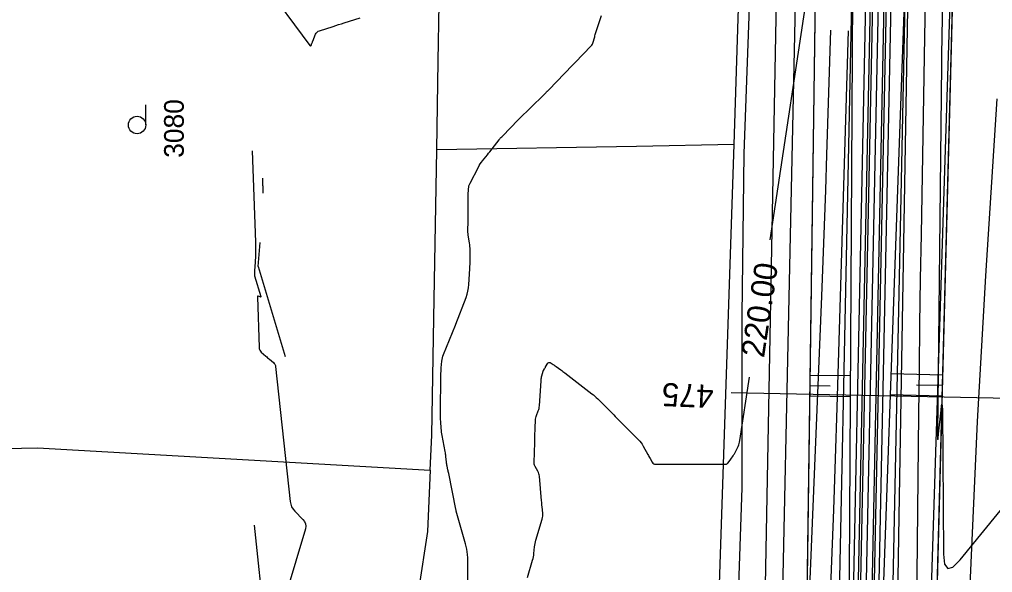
# Model space of a CAD drawing. Extents: x -534410 to -534262, y -1190162 to -1189584.
# Drawn here: x -534360.56 to -534318.59, y -1190105.52 to -1190081.68 of the extents above; entities that cross this region are included whole.
import ezdxf

# ---------------------------------------------------------------- set-up
doc = ezdxf.new("R2010")
doc.units = 0
for name, color, linetype in [('07_ELEKTRO', 7, 'Continuous'), ('30', 7, 'Continuous'), ('31', 7, 'Continuous'), ('40', 7, 'Continuous'), ('_linie', 7, 'Continuous'), ('_N_osa', 7, 'Continuous'), ('_N_tenká', 7, 'Continuous'), ('_N_tenká_velmi', 7, 'Continuous'), ('_N_text', 7, 'Continuous'), ('_přístup', 7, 'Continuous'), ('_tenka', 7, 'Continuous'), ('_velmi_tenka', 7, 'Continuous'), ('Default', 7, 'Continuous'), ('Hranice parcel', 7, 'Continuous'), ('Parcelní čísla', 7, 'Continuous'), ('Značky kultur', 7, 'Continuous')]:
    doc.layers.add(name, color=color, linetype=linetype)

msp = doc.modelspace()

# ---------------------------------------------------------------- linework, layer by layer
at = {"layer": '07_ELEKTRO'}
msp.add_lwpolyline([(-534340.501, -1190135.539), (-534331.273, -1190133.27), (-534330.81, -1190133.08), (-534330.32, -1190132.66), (-534330.24, -1190132.17), (-534330.24, -1190130.93), (-534330.14, -1190126.19), (-534329.99, -1190122.81), (-534329.79, -1190121.43), (-534329.75, -1190115.24), (-534329.64, -1190109.01), (-534329.39, -1190101.86), (-534329.4, -1190094.43), (-534329.31, -1190087.46), (-534329.03, -1190079.95)], dxfattribs=at)
at = {"layer": '30'}
for points in [[(-534322.214, -1190078.674), (-534322.64, -1190103.1), (-534322.669, -1190104.87), (-534322.696, -1190106.64)], [(-534328.187, -1190091.169), (-534326.393, -1190079.271)], [(-534350.068, -1190080.059), (-534348.04, -1190082.803), (-534348.025, -1190082.818), (-534348.012, -1190082.822), (-534348, -1190082.815), (-534347.99, -1190082.797), (-534347.952, -1190082.702), (-534347.942, -1190082.679), (-534347.932, -1190082.655), (-534347.923, -1190082.632), (-534347.913, -1190082.608), (-534347.79, -1190082.313), (-534347.762, -1190082.261), (-534347.726, -1190082.219), (-534347.68, -1190082.186), (-534347.626, -1190082.162), (-534347.035, -1190081.975), (-534346.916, -1190081.937), (-534346.798, -1190081.9), (-534346.68, -1190081.862), (-534346.562, -1190081.825), (-534345.87, -1190081.605)], [(-534320.757, -1190081.035), (-534320.78, -1190082.323), (-534320.785, -1190082.645), (-534320.79, -1190082.967), (-534320.794, -1190083.289), (-534320.798, -1190083.611), (-534320.966, -1190099.541), (-534320.965, -1190099.735), (-534320.957, -1190099.8), (-534320.942, -1190099.736), (-534320.92, -1190099.543), (-534320.816, -1190098.516), (-534320.793, -1190098.324), (-534320.777, -1190098.26), (-534320.766, -1190098.325), (-534320.76, -1190098.519), (-534320.71, -1190104.719), (-534320.661, -1190105.153), (-534320.526, -1190105.34), (-534320.304, -1190105.279), (-534319.995, -1190104.97), (-534317.954, -1190102.463)], [(-534325.609, -1190107.213), (-534325.521, -1190105.013), (-534325.44, -1190102.812), (-534325.364, -1190100.611), (-534325.296, -1190098.409), (-534324.811, -1190082.164)], [(-534350.063, -1190088.845), (-534350.063, -1190088.524)], [(-534350.063, -1190088.845), (-534350.063, -1190089.165)], [(-534350.269, -1190092.319), (-534350.186, -1190091.287)], [(-534350.269, -1190092.319), (-534349.107, -1190096.209)], [(-534338.651, -1190105.731), (-534338.432, -1190104.986), (-534338.413, -1190104.915), (-534338.397, -1190104.843), (-534338.384, -1190104.771), (-534338.375, -1190104.698), (-534338.346, -1190104.404), (-534338.336, -1190104.331), (-534338.324, -1190104.258), (-534338.308, -1190104.186), (-534338.289, -1190104.115), (-534338.02, -1190103.212), (-534338.005, -1190103.147), (-534337.995, -1190103.083), (-534337.992, -1190103.017), (-534337.995, -1190102.951), (-534338.022, -1190102.686), (-534338.028, -1190102.619), (-534338.034, -1190102.553), (-534338.041, -1190102.486), (-534338.047, -1190102.42), (-534338.141, -1190101.369), (-534338.149, -1190101.311), (-534338.163, -1190101.256), (-534338.182, -1190101.202), (-534338.207, -1190101.151), (-534338.32, -1190100.947), (-534338.344, -1190100.895), (-534338.36, -1190100.841), (-534338.369, -1190100.785), (-534338.37, -1190100.728), (-534338.354, -1190100.392), (-534338.351, -1190100.316), (-534338.348, -1190100.241), (-534338.345, -1190100.165), (-534338.343, -1190100.09), (-534338.331, -1190099.575), (-534338.329, -1190099.502), (-534338.327, -1190099.429), (-534338.324, -1190099.356), (-534338.321, -1190099.283), (-534338.306, -1190098.952), (-534338.301, -1190098.899), (-534338.293, -1190098.846), (-534338.28, -1190098.794), (-534338.263, -1190098.743), (-534338.186, -1190098.541), (-534338.168, -1190098.49), (-534338.155, -1190098.439), (-534338.146, -1190098.386), (-534338.14, -1190098.333), (-534338.069, -1190097.247), (-534338.065, -1190097.206), (-534338.06, -1190097.165), (-534338.053, -1190097.125), (-534338.044, -1190097.085), (-534337.997, -1190096.888), (-534337.991, -1190096.866), (-534337.983, -1190096.846), (-534337.974, -1190096.826), (-534337.963, -1190096.807), (-534337.917, -1190096.731), (-534337.906, -1190096.713), (-534337.894, -1190096.694), (-534337.883, -1190096.674), (-534337.872, -1190096.655), (-534337.781, -1190096.497), (-534337.76, -1190096.47), (-534337.736, -1190096.457), (-534337.709, -1190096.457), (-534337.678, -1190096.469), (-534337.547, -1190096.545), (-534337.515, -1190096.565), (-534337.483, -1190096.585), (-534337.452, -1190096.607), (-534337.422, -1190096.629), (-534337.221, -1190096.779), (-534337.178, -1190096.812), (-534337.134, -1190096.845), (-534337.091, -1190096.878), (-534337.048, -1190096.911), (-534335.874, -1190097.811), (-534335.809, -1190097.862), (-534335.746, -1190097.915), (-534335.684, -1190097.97), (-534335.624, -1190098.026), (-534335.386, -1190098.254), (-534335.327, -1190098.312), (-534335.268, -1190098.37), (-534335.21, -1190098.428), (-534335.153, -1190098.487), (-534334.924, -1190098.725), (-534334.867, -1190098.785), (-534334.81, -1190098.844), (-534334.752, -1190098.903), (-534334.694, -1190098.961), (-534333.865, -1190099.79), (-534333.806, -1190099.853), (-534333.753, -1190099.919), (-534333.705, -1190099.989), (-534333.661, -1190100.063), (-534333.461, -1190100.434), (-534333.438, -1190100.476), (-534333.415, -1190100.517), (-534333.392, -1190100.558), (-534333.367, -1190100.599), (-534333.27, -1190100.763), (-534333.243, -1190100.799), (-534333.21, -1190100.824), (-534333.171, -1190100.839), (-534333.126, -1190100.845), (-534330.096, -1190100.845), (-534330.071, -1190100.842), (-534330.048, -1190100.834), (-534330.028, -1190100.82), (-534330.011, -1190100.801), (-534329.916, -1190100.671), (-534329.885, -1190100.628), (-534329.786, -1190100.492), (-534329.765, -1190100.462), (-534329.746, -1190100.431), (-534329.728, -1190100.399), (-534329.711, -1190100.367), (-534329.57, -1190100.078), (-534329.543, -1190100.018), (-534329.521, -1190099.956), (-534329.504, -1190099.894), (-534329.492, -1190099.829), (-534329.081, -1190097.102)], [(-534350.446, -1190103.47), (-534349.99, -1190107.693)]]:
    msp.add_lwpolyline(points, dxfattribs=at)
at = {"layer": '31'}
for points in [[(-534321.501, -1190080.881), (-534321.531, -1190082.418), (-534321.679, -1190090.939), (-534321.711, -1190092.871), (-534321.74, -1190094.804), (-534321.765, -1190096.736), (-534321.787, -1190098.669), (-534321.992, -1190118.118)], [(-534341.225, -1190108.729), (-534341.225, -1190104.959), (-534341.227, -1190104.902), (-534341.23, -1190104.845), (-534341.235, -1190104.788), (-534341.242, -1190104.732), (-534341.275, -1190104.505), (-534341.284, -1190104.449), (-534341.295, -1190104.393), (-534341.308, -1190104.338), (-534341.322, -1190104.283), (-534341.723, -1190102.87), (-534341.726, -1190102.856), (-534341.731, -1190102.837), (-534341.734, -1190102.826), (-534341.74, -1190102.803), (-534341.743, -1190102.793), (-534341.745, -1190102.783), (-534342.05, -1190101.249), (-534342.058, -1190101.208), (-534342.067, -1190101.168), (-534342.075, -1190101.127), (-534342.084, -1190101.087), (-534342.121, -1190100.925), (-534342.129, -1190100.885), (-534342.136, -1190100.844), (-534342.142, -1190100.803), (-534342.147, -1190100.762), (-534342.17, -1190100.517), (-534342.176, -1190100.462), (-534342.183, -1190100.408), (-534342.191, -1190100.354), (-534342.201, -1190100.3), (-534342.331, -1190099.612), (-534342.344, -1190099.536), (-534342.355, -1190099.46), (-534342.364, -1190099.384), (-534342.371, -1190099.307), (-534342.394, -1190098.999), (-534342.4, -1190098.921), (-534342.403, -1190098.844), (-534342.406, -1190098.767), (-534342.406, -1190098.69), (-534342.407, -1190098.346), (-534342.407, -1190098.263), (-534342.406, -1190098.18), (-534342.405, -1190098.097), (-534342.402, -1190098.014), (-534342.39, -1190097.646), (-534342.387, -1190097.566), (-534342.386, -1190097.486), (-534342.385, -1190097.406), (-534342.385, -1190097.325), (-534342.386, -1190096.993), (-534342.385, -1190096.919), (-534342.383, -1190096.845), (-534342.379, -1190096.77), (-534342.373, -1190096.696), (-534342.348, -1190096.4), (-534342.339, -1190096.327), (-534342.324, -1190096.255), (-534342.304, -1190096.184), (-534342.278, -1190096.115), (-534341.755, -1190094.859), (-534341.753, -1190094.853), (-534341.751, -1190094.839), (-534341.749, -1190094.833), (-534341.743, -1190094.814), (-534341.741, -1190094.808), (-534341.304, -1190093.659), (-534341.257, -1190093.522), (-534341.222, -1190093.383), (-534341.196, -1190093.241), (-534341.182, -1190093.098), (-534341.139, -1190092.42), (-534341.134, -1190092.324), (-534341.13, -1190092.228), (-534341.128, -1190092.132), (-534341.127, -1190092.037), (-534341.127, -1190091.617), (-534341.129, -1190091.539), (-534341.133, -1190091.461), (-534341.141, -1190091.384), (-534341.153, -1190091.306), (-534341.207, -1190090.976), (-534341.217, -1190090.91), (-534341.222, -1190090.844), (-534341.225, -1190090.778), (-534341.224, -1190090.711), (-534341.215, -1190090.445), (-534341.213, -1190090.378), (-534341.212, -1190090.312), (-534341.211, -1190090.245), (-534341.21, -1190090.179), (-534341.21, -1190089.51), (-534341.21, -1190089.444), (-534341.209, -1190089.377), (-534341.208, -1190089.311), (-534341.205, -1190089.244), (-534341.195, -1190088.978), (-534341.189, -1190088.912), (-534341.176, -1190088.848), (-534341.156, -1190088.786), (-534341.129, -1190088.726), (-534340.772, -1190088.039), (-534340.732, -1190087.966), (-534340.689, -1190087.896), (-534340.642, -1190087.829), (-534340.591, -1190087.763), (-534340.381, -1190087.506), (-534340.329, -1190087.442), (-534340.277, -1190087.377), (-534340.226, -1190087.312), (-534340.175, -1190087.247), (-534339.878, -1190086.862), (-534339.872, -1190086.853), (-534339.865, -1190086.844), (-534339.859, -1190086.836), (-534339.852, -1190086.827), (-534339.827, -1190086.791), (-534339.821, -1190086.782), (-534339.813, -1190086.774), (-534339.805, -1190086.767), (-534339.797, -1190086.76), (-534339.761, -1190086.735), (-534339.752, -1190086.729), (-534339.744, -1190086.722), (-534339.736, -1190086.714), (-534339.728, -1190086.707), (-534339.051, -1190086.006), (-534338.935, -1190085.888), (-534338.818, -1190085.77), (-534338.7, -1190085.653), (-534338.581, -1190085.537), (-534337.881, -1190084.86), (-534337.873, -1190084.852), (-534337.866, -1190084.844), (-534337.859, -1190084.836), (-534337.852, -1190084.827), (-534337.826, -1190084.792), (-534337.819, -1190084.784), (-534337.812, -1190084.776), (-534337.804, -1190084.768), (-534337.796, -1190084.762), (-534337.761, -1190084.736), (-534337.752, -1190084.729), (-534337.744, -1190084.722), (-534337.736, -1190084.714), (-534337.728, -1190084.707), (-534337.051, -1190084.006), (-534336.936, -1190083.887), (-534336.82, -1190083.767), (-534336.705, -1190083.648), (-534336.59, -1190083.528), (-534335.906, -1190082.817), (-534335.875, -1190082.781), (-534335.85, -1190082.742), (-534335.83, -1190082.7), (-534335.815, -1190082.655), (-534335.767, -1190082.469), (-534335.755, -1190082.423), (-534335.742, -1190082.377), (-534335.728, -1190082.331), (-534335.714, -1190082.285), (-534335.462, -1190081.509)], [(-534326.603, -1190109.308), (-534325.953, -1190093.609), (-534325.893, -1190092.086), (-534325.836, -1190090.563), (-534325.784, -1190089.04), (-534325.737, -1190087.517), (-534325.576, -1190082.135)], [(-534350.522, -1190087.342), (-534350.387, -1190091.269), (-534350.387, -1190091.289), (-534350.387, -1190091.309), (-534350.387, -1190091.39), (-534350.387, -1190091.733), (-534350.387, -1190091.814), (-534350.387, -1190091.855), (-534350.387, -1190091.865), (-534350.387, -1190091.875), (-534350.387, -1190091.885), (-534350.388, -1190091.895), (-534350.414, -1190092.346), (-534350.416, -1190092.378), (-534350.418, -1190092.411), (-534350.42, -1190092.443), (-534350.423, -1190092.476), (-534350.433, -1190092.606), (-534350.434, -1190092.639), (-534350.433, -1190092.671), (-534350.428, -1190092.703), (-534350.42, -1190092.734), (-534350.158, -1190093.612), (-534350.155, -1190093.629), (-534350.158, -1190093.639), (-534350.169, -1190093.642), (-534350.185, -1190093.637), (-534350.266, -1190093.603), (-534350.283, -1190093.599), (-534350.295, -1190093.602), (-534350.303, -1190093.612), (-534350.304, -1190093.63), (-534350.229, -1190095.822), (-534350.221, -1190095.879), (-534350.203, -1190095.931), (-534350.174, -1190095.978), (-534350.133, -1190096.02), (-534349.942, -1190096.185), (-534349.901, -1190096.22), (-534349.86, -1190096.255), (-534349.819, -1190096.29), (-534349.777, -1190096.324), (-534349.612, -1190096.462), (-534349.575, -1190096.499), (-534349.547, -1190096.541), (-534349.528, -1190096.587), (-534349.517, -1190096.639), (-534348.889, -1190102.454), (-534348.867, -1190102.573), (-534348.826, -1190102.683), (-534348.766, -1190102.783), (-534348.687, -1190102.876), (-534348.337, -1190103.226), (-534348.265, -1190103.318), (-534348.223, -1190103.417), (-534348.213, -1190103.524), (-534348.233, -1190103.639), (-534349.895, -1190109.203)]]:
    msp.add_lwpolyline(points, dxfattribs=at)
at = {"layer": '_linie'}
for points in [[(-534351.8, -1189951.99), (-534346.88, -1189964.25), (-534328.11, -1190005.55), (-534325.796, -1190021.686), (-534325.86, -1190050.97), (-534326.22, -1190078.56), (-534326.79, -1190120.4), (-534329.12, -1190134.93), (-534323.49, -1190133.89), (-534321.38, -1190121.46), (-534319.59, -1190053.22), (-534320.45, -1190021.195), (-534322.75, -1190003.33), (-534340.65, -1189960.04), (-534344.52, -1189948.89)], [(-534347.45, -1189950.137), (-534345.54, -1189954.54), (-534325.02, -1190005.35), (-534322.054, -1190021.393), (-534321.72, -1190051.56), (-534322.31, -1190078.15), (-534323.81, -1190120.37), (-534326.521, -1190134.45)], [(-534328.194, -1190134.759), (-534324.85, -1190120.45), (-534324.6, -1190078.17), (-534323.54, -1190051.92), (-534323.273, -1190021.516), (-534325.81, -1190005.43), (-534346.66, -1189954.59), (-534348.342, -1189950.518)]]:
    msp.add_lwpolyline(points, dxfattribs=at)
at = {"layer": '_N_osa'}
msp.add_lwpolyline([(-534327.357, -1190134.604), (-534324.33, -1190120.41), (-534323.455, -1190078.16), (-534322.63, -1190051.74), (-534322.663, -1190021.455), (-534325.415, -1190005.39), (-534346.1, -1189954.565), (-534347.892, -1189950.326)], dxfattribs=at)
at = {"layer": '_N_tenká'}
for points in [[(-534326.133, -1190134.378), (-534323.183, -1190120.543), (-534322.305, -1190078.19), (-534321.48, -1190051.757), (-534321.513, -1190021.356), (-534324.303, -1190005.072), (-534345.038, -1189954.124), (-534346.832, -1189949.878)], [(-534327.623, -1190134.654), (-534324.579, -1190120.381), (-534323.705, -1190078.154), (-534322.88, -1190051.736), (-534322.913, -1190021.476), (-534325.657, -1190005.459), (-534346.331, -1189954.661), (-534348.122, -1189950.423)], [(-534327.091, -1190134.555), (-534324.081, -1190120.439), (-534323.205, -1190078.166), (-534322.38, -1190051.744), (-534322.413, -1190021.433), (-534325.173, -1190005.321), (-534345.869, -1189954.469), (-534347.661, -1189950.228)], [(-534328.581, -1190134.83), (-534325.477, -1190120.277), (-534324.605, -1190078.13), (-534323.78, -1190051.723), (-534323.813, -1190021.553), (-534326.527, -1190005.708), (-534347.162, -1189955.006), (-534348.951, -1189950.773)]]:
    msp.add_lwpolyline(points, dxfattribs=at)
at = {"layer": '_N_tenká_velmi'}
for points in [[(-534326.985, -1190134.536), (-534323.981, -1190120.45), (-534323.105, -1190078.169), (-534322.28, -1190051.745), (-534322.313, -1190021.425), (-534325.076, -1190005.293), (-534345.777, -1189954.431), (-534347.569, -1189950.189)], [(-534326.772, -1190134.496), (-534323.781, -1190120.474), (-534322.905, -1190078.174), (-534322.08, -1190051.748), (-534322.113, -1190021.407), (-534324.883, -1190005.238), (-534345.592, -1189954.354), (-534347.385, -1189950.112)], [(-534327.943, -1190134.713), (-534324.879, -1190120.346), (-534324.005, -1190078.146), (-534323.18, -1190051.732), (-534323.213, -1190021.502), (-534325.947, -1190005.542), (-534346.608, -1189954.776), (-534348.398, -1189950.54)], [(-534327.73, -1190134.673), (-534324.679, -1190120.37), (-534323.805, -1190078.151), (-534322.98, -1190051.735), (-534323.013, -1190021.485), (-534325.754, -1190005.487), (-534346.423, -1189954.699), (-534348.214, -1189950.462)]]:
    msp.add_lwpolyline(points, dxfattribs=at)
at = {"layer": '_N_text'}
msp.add_lwpolyline([(-534317.865, -1190098.015), (-534329.862, -1190097.767)], dxfattribs=at)
at = {"layer": '_přístup'}
msp.add_lwpolyline([(-534330.552, -1190135.191), (-534328.648, -1190119.819), (-534326.845, -1190024.247), (-534332.805, -1189999.297), (-534354.454, -1189948.317)], dxfattribs=at)
at = {"layer": '_tenka'}
for points in [[(-534351.8, -1189951.99), (-534346.88, -1189964.25), (-534328.11, -1190005.55), (-534325.796, -1190021.686), (-534325.86, -1190050.97), (-534326.22, -1190078.56), (-534326.79, -1190120.4), (-534329.12, -1190134.93), (-534323.49, -1190133.89), (-534321.38, -1190121.46), (-534319.59, -1190053.22), (-534320.45, -1190021.195), (-534322.75, -1190003.33), (-534340.65, -1189960.04), (-534344.52, -1189948.89)], [(-534327.55, -1190134.64), (-534323.49, -1190133.89), (-534321.38, -1190121.46), (-534319.59, -1190053.22), (-534320.45, -1190021.195), (-534322.75, -1190003.33), (-534340.65, -1189960.04), (-534344.52, -1189948.89)], [(-534347.45, -1189950.137), (-534345.54, -1189954.54), (-534325.02, -1190005.35), (-534322.054, -1190021.393), (-534321.72, -1190051.56), (-534322.31, -1190078.15), (-534323.81, -1190120.37), (-534326.521, -1190134.45)], [(-534347.45, -1189950.137), (-534345.54, -1189954.54), (-534325.02, -1190005.35), (-534322.054, -1190021.393), (-534321.72, -1190051.56), (-534322.31, -1190078.15), (-534323.81, -1190120.37), (-534326.521, -1190134.45)], [(-534328.194, -1190134.759), (-534324.85, -1190120.45), (-534324.6, -1190078.17), (-534323.54, -1190051.92), (-534323.273, -1190021.516), (-534325.81, -1190005.43), (-534346.66, -1189954.59), (-534348.342, -1189950.518)], [(-534328.194, -1190134.759), (-534324.85, -1190120.45), (-534324.6, -1190078.17), (-534323.54, -1190051.92), (-534323.273, -1190021.516), (-534325.81, -1190005.43), (-534346.66, -1189954.59), (-534348.342, -1189950.518)], [(-534351.8, -1189951.99), (-534346.88, -1189964.25), (-534328.11, -1190005.55), (-534325.796, -1190021.686), (-534325.86, -1190050.97), (-534326.22, -1190078.56), (-534326.79, -1190120.4), (-534329.12, -1190134.93), (-534327.55, -1190134.64)]]:
    msp.add_lwpolyline(points, dxfattribs=at)
at = {"layer": '_velmi_tenka'}
for p, q in [((-534326.471, -1190097.004), (-534324.708, -1190097.03)), ((-534320.74, -1190097.012), (-534322.984, -1190096.958)), ((-534326.477, -1190097.454), (-534325.596, -1190097.467)), ((-534320.75, -1190097.461), (-534321.872, -1190097.435)), ((-534326.484, -1190097.904), (-534324.721, -1190097.93)), ((-534320.761, -1190097.911), (-534323.005, -1190097.858))]:
    msp.add_line(p, q, dxfattribs=at)
at = {"layer": 'Default'}
for p, q in [((-534321.38, -1190121.46), (-534319.59, -1190053.22)), ((-534326.22, -1190078.56), (-534326.79, -1190120.4))]:
    msp.add_line(p, q, dxfattribs=at)
at = {"layer": 'Hranice parcel'}
msp.add_line((-534329.74, -1190087.07), (-534329.49, -1190079.46), dxfattribs=at)
for points in [[(-534333.99, -1189993.03), (-534331.98, -1189997.67), (-534327.34, -1190013.08), (-534325.48, -1190021.81), (-534326.93, -1190073), (-534328.13, -1190128.3), (-534328.71, -1190131.86)], [(-534322.11, -1190134.26), (-534321.95, -1190128.7), (-534320.16, -1190072.85), (-534318.8, -1190033.53)], [(-534342.57, -1190087.3), (-534342.5, -1190083.48), (-534342.42, -1190078.52), (-534342.37, -1190071.42)], [(-534320.3, -1190128.29), (-534320.41, -1190126.09), (-534320.16, -1190119.52), (-534319.24, -1190099.01), (-534318.88, -1190092.72), (-534318.39, -1190085.1)], [(-534342.85, -1190101.1), (-534342.78, -1190099.6), (-534342.69, -1190094.55), (-534342.57, -1190087.3)], [(-534329.74, -1190087.07), (-534333.95, -1190087.15), (-534342.57, -1190087.3)], [(-534331.23, -1190131.88), (-534330.53, -1190110.76), (-534329.74, -1190087.07)], [(-534367.47, -1190102.26), (-534363.21, -1190102.26), (-534363.24, -1190100.22), (-534359.78, -1190100.14), (-534342.85, -1190101.1)], [(-534342.85, -1190101.1), (-534342.97, -1190103.75), (-534343.35, -1190106.28), (-534343.41, -1190108.25)]]:
    msp.add_lwpolyline(points, dxfattribs=at)
at = {"layer": 'Značky kultur'}
msp.add_line((-534355.117, -1190086.225), (-534355.117, -1190085.35), dxfattribs=at)
msp.add_circle((-534355.492, -1190086.225), 0.375, dxfattribs=at)

# ---------------------------------------------------------------- texts
at = {"layer": '40'}
msp.add_text('220.00', height=1, rotation=81.4277, dxfattribs=at).set_placement((-534328.453, -1190096.289))
at = {"layer": '_N_text'}
msp.add_text('475', height=1, rotation=177.5871, dxfattribs=at).set_placement((-534330.606, -1190097.433))
at = {"layer": 'Parcelní čísla'}
msp.add_text('3080', height=0.85, rotation=90, dxfattribs=at).set_placement((-534353.477, -1190087.64))

doc.saveas('drawing.dxf')
